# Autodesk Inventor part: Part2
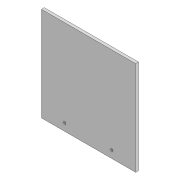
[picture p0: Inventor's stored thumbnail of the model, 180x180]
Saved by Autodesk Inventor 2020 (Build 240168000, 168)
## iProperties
Created: 2019-12
Part Number: Part2
Material: Generic
Document SubType Name: Modeling
Designer: Dell
Density: 1 g/cm^3
Appearance: Default
Author: Dell
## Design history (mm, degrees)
sketch "Sketch1"
  geometry: L1 (0, 0)-(200, 0); L2 (200, 0)-(200, 200); L3 (200, 200)-(0, 200); L4 (0, 200)-(0, 0)
  constraints: 8 end point, 2 parallel, 1 horizontal, 1 perpendicular
  dimensions: "d0" = 200 distance of L3.end L2.end; "d1" = 200 distance of L2.end L1.end
extrude "Extrusion1" new body sketch "Sketch1" distance "d2" = 6; taper "d3" = 0 deg
sketch "Sketch2"
  geometry: C1 r 2.5 at (49.47, 15.795); 1 further point
  constraints: 1 centre point
  dimensions: "d4" = 5 diameter of C1
extrude "Extrusion2" cut sketch "Sketch2" distance "d5" = 6; taper "d6" = 0 deg
sketch "Sketch3"
  geometry: C1 r 2.5 at (149.602, 15.795); 1 further point
  constraints: 1 centre point
  dimensions: "d7" = 5 diameter of C1
extrude "Extrusion3" cut sketch "Sketch3" distance "d8" = 6; taper "d9" = 0 deg
body "Solid1"
